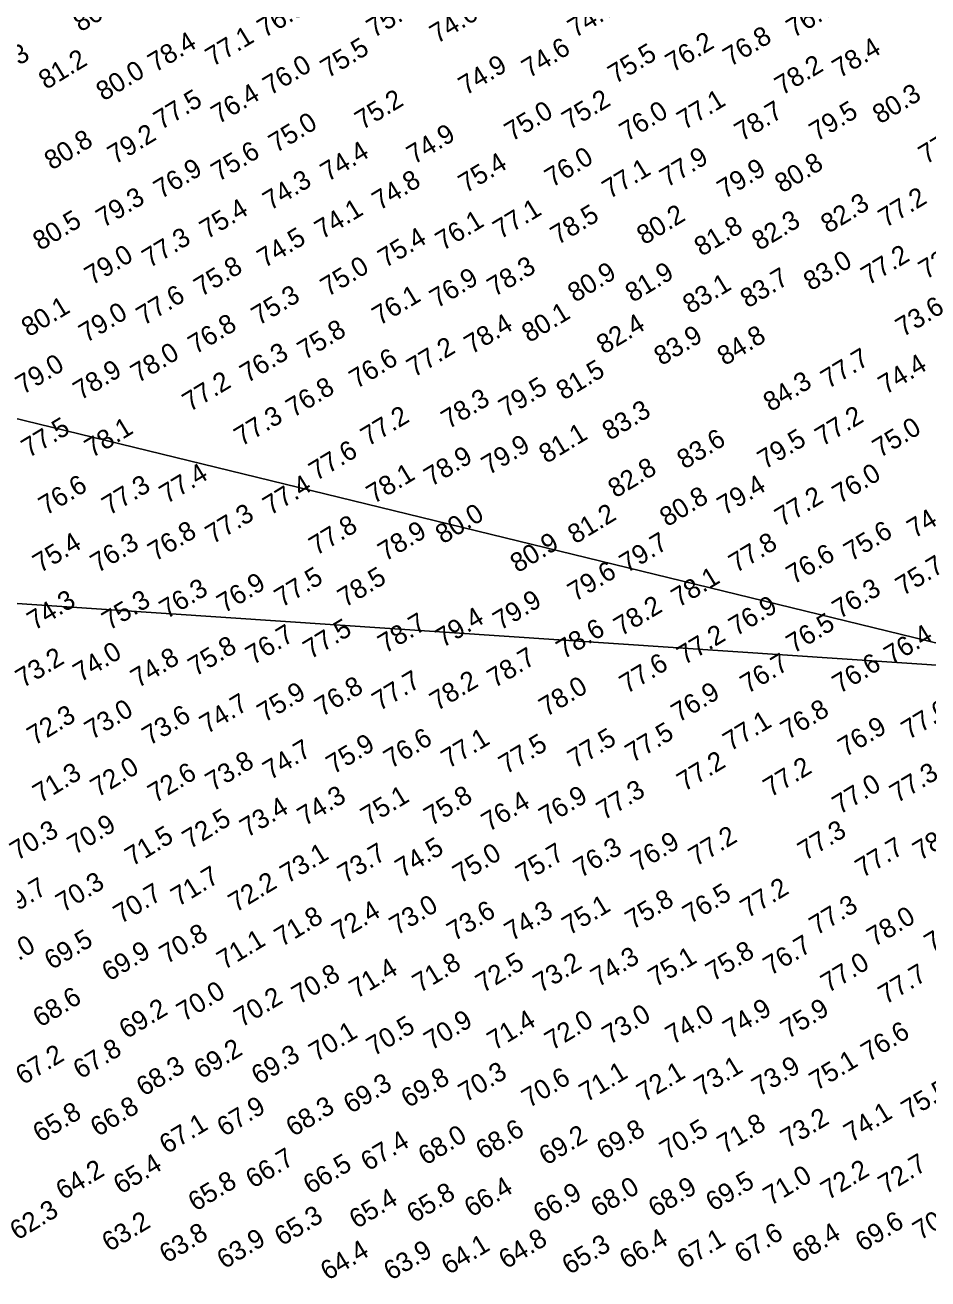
# Model space of a CAD drawing. Extents: x 403671 to 408751, y 1189919 to 1194265.
# Drawn here: x 405477 to 405948, y 1191463 to 1192117 of the extents above; entities that cross this region are included whole.
import ezdxf

# ---------------------------------------------------------------- set-up
doc = ezdxf.new("R2010")
doc.units = 0
for name, color, linetype in [('C-CHAN-POIT', 7, 'Continuous'), ('C-CHAN-WIDE', 7, 'Continuous'), ('V-TOPO-SOUN', 7, 'Continuous')]:
    doc.layers.add(name, color=color, linetype=linetype)

msp = doc.modelspace()

# ---------------------------------------------------------------- linework, layer by layer
at = {"layer": 'C-CHAN-POIT'}
msp.add_line((404840.85, 1192065.98), (406017.44, 1191779.04), dxfattribs=at)
at = {"layer": 'C-CHAN-WIDE'}
msp.add_line((404790.92, 1191861.25), (406017.44, 1191779.04), dxfattribs=at)

# ---------------------------------------------------------------- texts
at = {"layer": 'V-TOPO-SOUN'}
for s, p in [('80.5 ', (405505.78, 1192113.31)), ('76.5 ', (405601.78, 1192110.3)), ('75.0 ', (405658.77, 1192110.3)), ('74.7 ', (405763.75, 1192110.3)), ('76.7 ', (405877.76, 1192110.3)), ('74.6 ', (405691.77, 1192107.31)), ('78.4 ', (405544.76, 1192092.32)), ('77.1 ', (405574.78, 1192095.3)), ('76.2 ', (405814.77, 1192092.32)), ('76.8 ', (405844.76, 1192095.3)), ('80.3 ', (405457.78, 1192086.31)), ('75.5 ', (405634.78, 1192089.3)), ('74.6 ', (405739.77, 1192089.3)), ('75.5 ', (405784.78, 1192086.31)), ('78.4 ', (405901.78, 1192089.3)), ('81.2 ', (405487.77, 1192083.29)), ('76.0 ', (405604.76, 1192080.31)), ('74.9 ', (405706.76, 1192080.31)), ('78.2 ', (405871.76, 1192080.31)), ('80.0 ', (405517.76, 1192077.32)), ('76.4 ', (405577.76, 1192065.32)), ('80.3 ', (405922.77, 1192065.32)), ('77.5 ', (405547.78, 1192062.3)), ('75.2 ', (405652.76, 1192062.3)), ('75.2 ', (405760.77, 1192062.3)), ('77.1 ', (405820.77, 1192062.3)), ('75.0 ', (405730.78, 1192056.29)), ('76.0 ', (405790.75, 1192056.29)), ('78.7 ', (405850.76, 1192056.29)), ('79.5 ', (405889.77, 1192056.29)), ('75.0 ', (405607.78, 1192050.32)), ('80.8 ', (405490.75, 1192041.3)), ('79.2 ', (405523.76, 1192044.32)), ('74.9 ', (405679.76, 1192044.32)), ('77.5 ', (405946.76, 1192044.32)), ('75.6 ', (405577.76, 1192035.3)), ('74.4 ', (405634.78, 1192035.3)), ('76.0 ', (405751.78, 1192032.31)), ('77.9 ', (405811.75, 1192032.31)), ('76.9 ', (405547.78, 1192026.31)), ('75.4 ', (405706.76, 1192029.32)), ('77.1 ', (405781.76, 1192026.31)), ('79.9 ', (405841.77, 1192026.31)), ('80.8 ', (405871.76, 1192029.32)), ('74.3 ', (405604.76, 1192020.3)), ('74.8 ', (405661.75, 1192020.3)), ('79.3 ', (405517.76, 1192011.31)), ('82.3 ', (405895.77, 1192008.29)), ('77.2 ', (405925.76, 1192011.31)), ('80.5 ', (405484.75, 1191999.3)), ('75.4 ', (405571.76, 1192005.31)), ('74.1 ', (405631.76, 1192005.31)), ('77.1 ', (405724.78, 1192005.31)), ('78.5 ', (405754.76, 1192002.32)), ('80.2 ', (405799.78, 1192002.32)), ('82.3 ', (405859.78, 1191999.3)), ('76.1 ', (405694.76, 1191999.3)), ('81.8 ', (405829.76, 1191996.32)), ('77.3 ', (405541.77, 1191990.32)), ('74.5 ', (405601.78, 1191990.32)), ('75.4 ', (405664.77, 1191990.32)), ('79.0 ', (405511.75, 1191981.29)), ('77.2 ', (405916.77, 1191981.29)), ('73.0 ', (405946.76, 1191984.31)), ('75.8 ', (405568.77, 1191975.32)), ('75.0 ', (405634.78, 1191975.32)), ('78.3 ', (405721.76, 1191975.32)), ('83.0 ', (405886.75, 1191978.31)), ('76.9 ', (405691.77, 1191969.32)), ('80.9 ', (405763.75, 1191972.3)), ('81.9 ', (405793.77, 1191972.3)), ('83.7 ', (405853.78, 1191969.32)), ('77.6 ', (405538.75, 1191960.3)), ('75.3 ', (405598.76, 1191960.3)), ('83.1 ', (405823.76, 1191966.3)), ('80.1 ', (405478.78, 1191954.32)), ('76.1 ', (405661.75, 1191960.3)), ('73.6 ', (405934.78, 1191954.32)), ('79.0 ', (405508.77, 1191951.31)), ('80.1 ', (405739.77, 1191951.31)), ('76.8 ', (405565.75, 1191945.3)), ('75.8 ', (405622.78, 1191942.32)), ('78.4 ', (405709.78, 1191945.3)), ('82.4 ', (405778.78, 1191945.3)), ('83.9 ', (405808.77, 1191939.3)), ('84.8 ', (405841.77, 1191939.3)), ('78.0 ', (405535.77, 1191930.31)), ('76.3 ', (405592.76, 1191930.31)), ('76.6 ', (405649.78, 1191927.32)), ('77.2 ', (405679.76, 1191933.29)), ('77.7 ', (405895.77, 1191927.32)), ('79.0 ', (405475.76, 1191924.3)), ('78.9 ', (405505.78, 1191921.32)), ('81.5 ', (405757.78, 1191921.32)), ('74.4 ', (405925.76, 1191924.3)), ('77.2 ', (405562.77, 1191915.32)), ('84.3 ', (405865.75, 1191915.32)), ('76.8 ', (405616.77, 1191912.3)), ('79.5 ', (405727.76, 1191912.3)), ('78.3 ', (405697.78, 1191906.29)), ('77.3 ', (405589.77, 1191897.3)), ('77.2 ', (405655.78, 1191897.3)), ('83.3 ', (405781.76, 1191900.32)), ('77.2 ', (405892.76, 1191897.3)), ('77.5 ', (405478.78, 1191891.3)), ('78.1 ', (405511.75, 1191891.3)), ('75.0 ', (405922.77, 1191891.3)), ('79.9 ', (405718.77, 1191882.31)), ('81.1 ', (405748.76, 1191888.31)), ('83.6 ', (405820.77, 1191885.3)), ('79.5 ', (405862.77, 1191885.3)), ('77.6 ', (405628.78, 1191879.29)), ('78.9 ', (405688.75, 1191876.31)), ('82.8 ', (405784.78, 1191870.3)), ('77.4 ', (405550.76, 1191867.32)), ('78.1 ', (405658.77, 1191867.32)), ('76.0 ', (405901.78, 1191867.32)), ('76.6 ', (405487.77, 1191861.31)), ('77.3 ', (405520.77, 1191861.31)), ('77.4 ', (405604.76, 1191861.31)), ('79.4 ', (405841.77, 1191861.31)), ('77.2 ', (405871.76, 1191855.31)), ('80.8 ', (405811.75, 1191855.31)), ('74.6 ', (405940.75, 1191849.31)), ('77.3 ', (405574.78, 1191846.32)), ('80.0 ', (405694.76, 1191846.32)), ('81.2 ', (405763.75, 1191846.32)), ('76.8 ', (405544.76, 1191837.3)), ('77.8 ', (405628.78, 1191840.32)), ('78.9 ', (405664.77, 1191837.3)), ('75.6 ', (405907.78, 1191837.3)), ('75.4 ', (405484.75, 1191831.29)), ('76.3 ', (405514.77, 1191831.29)), ('80.9 ', (405733.77, 1191831.29)), ('79.7 ', (405790.75, 1191831.29)), ('77.8 ', (405847.77, 1191831.29)), ('76.6 ', (405877.76, 1191825.32)), ('79.6 ', (405763.75, 1191816.3)), ('75.7 ', (405934.78, 1191819.32)), ('76.9 ', (405580.78, 1191810.3)), ('77.5 ', (405610.77, 1191813.31)), ('78.5 ', (405643.77, 1191813.31)), ('78.1 ', (405817.76, 1191813.31)), ('76.3 ', (405550.76, 1191807.31)), ('76.3 ', (405901.78, 1191807.31)), ('74.3 ', (405481.77, 1191801.31)), ('75.3 ', (405520.77, 1191801.31)), ('79.9 ', (405724.78, 1191801.31)), ('78.2 ', (405787.77, 1191798.32)), ('76.9 ', (405847.77, 1191798.32)), ('78.7 ', (405664.77, 1191789.3)), ('79.4 ', (405694.76, 1191792.32)), ('76.7 ', (405595.77, 1191783.29)), ('77.5 ', (405625.76, 1191786.31)), ('78.6 ', (405757.78, 1191786.31)), ('76.5 ', (405877.76, 1191789.3)), ('76.4 ', (405928.78, 1191783.29)), ('75.8 ', (405565.75, 1191777.32)), ('77.2 ', (405820.77, 1191783.29)), ('73.2 ', (405475.76, 1191771.32)), ('74.0 ', (405505.78, 1191774.31)), ('74.8 ', (405535.77, 1191771.32)), ('78.7 ', (405721.76, 1191771.32)), ('77.6 ', (405790.75, 1191768.3)), ('76.7 ', (405853.78, 1191768.3)), ('76.6 ', (405901.78, 1191768.3)), ('77.7 ', (405661.75, 1191759.31)), ('78.2 ', (405691.77, 1191759.31)), ('75.9 ', (405601.78, 1191753.31)), ('76.8 ', (405631.76, 1191756.29)), ('78.0 ', (405748.76, 1191756.29)), ('76.9 ', (405817.76, 1191753.31)), ('73.0 ', (405511.75, 1191744.32)), ('74.7 ', (405571.76, 1191747.3)), ('76.8 ', (405874.78, 1191744.32)), ('77.0 ', (405937.77, 1191744.32)), ('72.3 ', (405481.77, 1191741.3)), ('73.6 ', (405541.77, 1191741.3)), ('77.1 ', (405844.76, 1191738.31)), ('77.5 ', (405793.77, 1191732.31)), ('76.9 ', (405904.76, 1191735.3)), ('75.9 ', (405637.77, 1191726.31)), ('76.6 ', (405667.76, 1191729.29)), ('77.1 ', (405697.78, 1191729.29)), ('77.5 ', (405727.76, 1191726.31)), ('77.5 ', (405763.75, 1191729.29)), ('74.7 ', (405604.76, 1191723.32)), ('72.0 ', (405514.77, 1191714.3)), ('72.6 ', (405544.76, 1191711.31)), ('73.8 ', (405574.78, 1191717.32)), ('77.2 ', (405820.77, 1191717.32)), ('77.2 ', (405865.75, 1191714.3)), ('71.3 ', (405484.75, 1191711.31)), ('77.0 ', (405901.78, 1191705.31)), ('77.3 ', (405931.76, 1191711.31)), ('74.3 ', (405622.78, 1191699.31)), ('75.1 ', (405655.78, 1191699.31)), ('75.8 ', (405688.75, 1191699.31)), ('76.9 ', (405748.76, 1191699.31)), ('77.3 ', (405778.78, 1191702.32)), ('73.4 ', (405592.76, 1191693.3)), ('76.4 ', (405718.77, 1191696.32)), ('72.5 ', (405562.77, 1191687.3)), ('70.3 ', (405472.78, 1191681.29)), ('70.9 ', (405502.76, 1191684.31)), ('71.5 ', (405532.78, 1191678.31)), ('77.3 ', (405883.77, 1191681.29)), ('78.4 ', (405943.77, 1191681.29)), ('74.5 ', (405673.76, 1191672.3)), ('76.3 ', (405766.77, 1191672.3)), ('76.9 ', (405796.76, 1191675.32)), ('77.2 ', (405826.78, 1191678.31)), ('77.7 ', (405913.75, 1191672.3)), ('73.1 ', (405613.75, 1191669.32)), ('73.7 ', (405643.77, 1191669.32)), ('75.0 ', (405703.78, 1191669.32)), ('75.7 ', (405736.75, 1191669.32)), ('70.3 ', (405496.76, 1191654.29)), ('71.7 ', (405556.76, 1191657.31)), ('72.2 ', (405586.75, 1191654.29)), ('69.7 ', (405466.77, 1191651.31)), ('70.7 ', (405526.78, 1191648.32)), ('76.5 ', (405823.76, 1191648.32)), ('77.2 ', (405853.78, 1191651.31)), ('73.0 ', (405670.77, 1191642.32)), ('73.6 ', (405700.76, 1191639.3)), ('75.1 ', (405760.77, 1191642.32)), ('75.8 ', (405793.77, 1191645.3)), ('77.3 ', (405889.77, 1191642.32)), ('71.8 ', (405610.77, 1191636.31)), ('72.4 ', (405640.75, 1191639.3)), ('74.3 ', (405730.78, 1191639.3)), ('78.0 ', (405919.76, 1191636.31)), ('79.2 ', (405949.78, 1191633.3)), ('70.8 ', (405550.76, 1191627.32)), ('69.0 ', (405460.77, 1191621.32)), ('69.5 ', (405490.75, 1191624.31)), ('71.1 ', (405580.78, 1191624.31)), ('76.7 ', (405865.75, 1191621.32)), ('69.9 ', (405520.77, 1191618.3)), ('74.3 ', (405775.76, 1191615.32)), ('75.1 ', (405805.78, 1191615.32)), ('75.8 ', (405835.77, 1191618.3)), ('71.4 ', (405649.78, 1191609.31)), ('71.8 ', (405682.78, 1191612.3)), ('72.5 ', (405715.75, 1191612.3)), ('73.2 ', (405745.77, 1191612.3)), ('77.0 ', (405895.77, 1191612.3)), ('77.7 ', (405925.76, 1191606.29)), ('70.8 ', (405619.76, 1191606.29)), ('68.6 ', (405484.75, 1191594.32)), ('70.0 ', (405559.75, 1191597.3)), ('70.2 ', (405589.77, 1191594.32)), ('69.2 ', (405529.76, 1191588.31)), ('74.9 ', (405844.76, 1191588.31)), ('75.9 ', (405874.78, 1191588.31)), ('70.9 ', (405688.75, 1191582.31)), ('71.4 ', (405721.76, 1191582.31)), ('72.0 ', (405751.78, 1191582.31)), ('73.0 ', (405781.76, 1191585.3)), ('74.0 ', (405814.77, 1191585.3)), ('70.1 ', (405628.78, 1191576.31)), ('70.5 ', (405658.77, 1191579.29)), ('76.6 ', (405916.77, 1191576.31)), ('67.2 ', (405475.76, 1191564.3)), ('67.8 ', (405505.78, 1191567.32)), ('69.2 ', (405568.77, 1191567.32)), ('69.3 ', (405598.76, 1191564.3)), ('68.3 ', (405538.75, 1191558.3)), ('70.3 ', (405706.76, 1191555.31)), ('71.1 ', (405769.76, 1191555.31)), ('72.1 ', (405799.78, 1191555.31)), ('73.1 ', (405829.76, 1191558.3)), ('73.9 ', (405859.78, 1191558.3)), ('75.1 ', (405889.77, 1191561.31)), ('69.3 ', (405646.76, 1191549.31)), ('69.8 ', (405676.78, 1191552.32)), ('70.6 ', (405739.77, 1191552.32)), ('75.5 ', (405937.77, 1191546.32)), ('66.8 ', (405514.77, 1191537.3)), ('67.9 ', (405580.78, 1191537.3)), ('68.3 ', (405616.77, 1191537.3)), ('65.8 ', (405484.75, 1191534.31)), ('73.2 ', (405874.78, 1191531.29)), ('74.1 ', (405907.78, 1191534.31)), ('67.1 ', (405550.76, 1191528.31)), ('68.0 ', (405685.77, 1191522.3)), ('68.6 ', (405715.75, 1191525.32)), ('69.2 ', (405748.76, 1191522.3)), ('69.8 ', (405778.78, 1191525.32)), ('70.5 ', (405811.75, 1191525.32)), ('71.8 ', (405841.77, 1191528.31)), ('67.4 ', (405655.78, 1191519.32)), ('66.7 ', (405595.77, 1191510.3)), ('64.2 ', (405496.76, 1191504.29)), ('65.4 ', (405526.78, 1191507.31)), ('66.5 ', (405625.76, 1191507.31)), ('72.2 ', (405895.77, 1191504.29)), ('72.7 ', (405925.76, 1191507.31)), ('65.8 ', (405565.75, 1191498.32)), ('69.5 ', (405835.77, 1191498.32)), ('71.0 ', (405865.75, 1191501.31)), ('65.4 ', (405649.78, 1191489.3)), ('65.8 ', (405679.76, 1191492.32)), ('66.4 ', (405709.78, 1191495.3)), ('66.9 ', (405745.77, 1191492.32)), ('68.0 ', (405775.76, 1191495.3)), ('68.9 ', (405805.78, 1191495.3)), ('62.3 ', (405472.78, 1191483.3)), ('70.7 ', (405943.77, 1191483.3)), ('63.2 ', (405520.77, 1191477.32)), ('65.3 ', (405610.77, 1191480.31)), ('69.6 ', (405913.75, 1191477.32)), ('63.8 ', (405550.76, 1191471.32)), ('67.6 ', (405850.76, 1191471.32)), ('68.4 ', (405880.78, 1191471.32)), ('63.9 ', (405580.78, 1191468.3)), ('64.1 ', (405697.78, 1191465.32)), ('64.8 ', (405727.76, 1191468.3)), ('65.3 ', (405760.77, 1191465.32)), ('66.4 ', (405790.75, 1191468.3)), ('67.1 ', (405820.77, 1191468.3)), ('64.4 ', (405634.78, 1191462.3)), ('63.9 ', (405667.76, 1191462.3))]:
    msp.add_text(s, height=9.996, rotation=31.2939, dxfattribs=at).set_placement(p)

doc.saveas('drawing.dxf')
